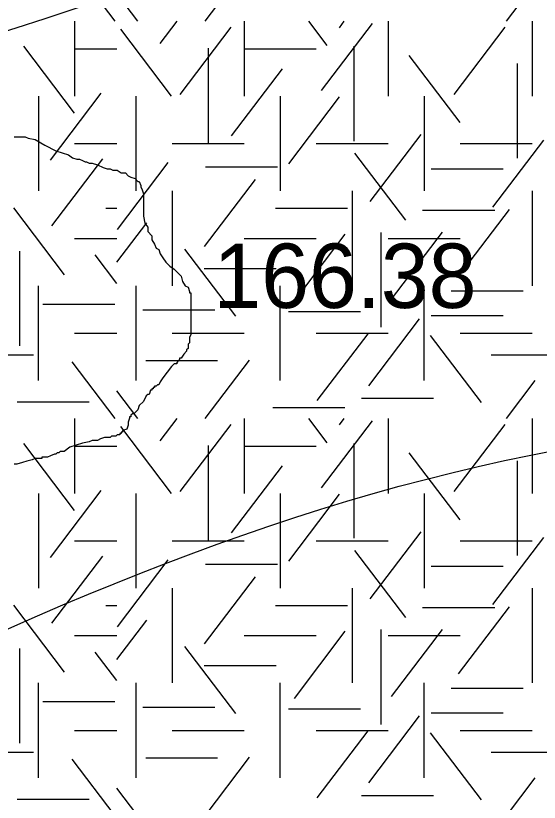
# Model space of a CAD drawing. Extents: x 419101 to 420177, y 4451541 to 4452254.
# Drawn here: x 419921.41 to 419931.17, y 4451588.77 to 4451603.44 of the extents above; entities that cross this region are included whole.
import ezdxf

# ---------------------------------------------------------------- set-up
doc = ezdxf.new("R2010")
doc.units = 0
for name, color, linetype in [('3_HALİHAZIR', 7, 'Continuous'), ('Level 3', 7, 'Continuous'), ('Level 41', 7, 'Continuous')]:
    doc.layers.add(name, color=color, linetype=linetype)

msp = doc.modelspace()

# ---------------------------------------------------------------- linework, layer by layer
at = {"layer": '3_HALİHAZIR'}
for points in [[(419839.353, 4451591.962), (419839.364, 4451591.971), (419844.374, 4451596.271), (419851.394, 4451601.551), (419855.474, 4451603.971), (419875.934, 4451611.761), (419891.494, 4451615.431), (419906.684, 4451617.851), (419924.462, 4451620.917), (419940.295, 4451639.301), (419940.435, 4451639.501), (419940.605, 4451639.681)], [(419830.585, 4451569.182), (419835.774, 4451573.831), (419840.974, 4451578.331), (419857.814, 4451590.841), (419892.084, 4451597.601), (419927.345, 4451605.321), (419938.763, 4451608.51), (419942.048, 4451608.213)], [(419823.158, 4451549.789), (419823.164, 4451549.79), (419829.854, 4451552.83), (419838.324, 4451557.73), (419864.054, 4451568.471), (419874.464, 4451571.841), (419888.954, 4451576.141), (419895.924, 4451578.691), (419906.074, 4451583.863), (419936.516, 4451595.874), (419942.649, 4451595.582)]]:
    msp.add_spline(points, degree=3, dxfattribs=at)
at = {"layer": 'Level 3'}
for points in [[(419921.378, 4451601.182), (419921.43, 4451601.182), (419921.508, 4451601.182), (419921.56, 4451601.182), (419921.586, 4451601.182), (419921.638, 4451601.156), (419921.768, 4451601.13), (419921.949, 4451601.026), (419922.157, 4451600.922), (419922.39, 4451600.844), (419922.468, 4451600.792), (419922.546, 4451600.766), (419922.598, 4451600.766), (419922.65, 4451600.74), (419922.701, 4451600.714), (419922.727, 4451600.714), (419922.779, 4451600.688), (419922.831, 4451600.688), (419922.935, 4451600.662), (419923.039, 4451600.61), (419923.116, 4451600.584), (419923.168, 4451600.584), (419923.22, 4451600.558), (419923.272, 4451600.558), (419923.298, 4451600.558), (419923.376, 4451600.507), (419923.454, 4451600.507), (419923.506, 4451600.455), (419923.557, 4451600.429), (419923.635, 4451600.403), (419923.687, 4451600.351), (419923.713, 4451600.351), (419923.739, 4451600.273), (419923.739, 4451600.247), (419923.765, 4451600.195), (419923.791, 4451600.117), (419923.791, 4451600.091), (419923.791, 4451600.013), (419923.791, 4451599.961), (419923.791, 4451599.883), (419923.791, 4451599.857), (419923.791, 4451599.779), (419923.791, 4451599.702), (419923.817, 4451599.572), (419923.869, 4451599.494), (419923.869, 4451599.416), (419923.947, 4451599.338), (419923.947, 4451599.26), (419923.998, 4451599.182), (419924.024, 4451599.104), (419924.076, 4451599.078), (419924.102, 4451599), (419924.154, 4451598.922), (419924.206, 4451598.845), (419924.284, 4451598.767), (419924.362, 4451598.715), (419924.413, 4451598.663), (419924.439, 4451598.637), (419924.491, 4451598.585), (419924.517, 4451598.481), (419924.569, 4451598.403), (419924.621, 4451598.377), (419924.647, 4451598.299), (419924.647, 4451598.273), (419924.673, 4451598.273), (419924.673, 4451598.247), (419924.673, 4451598.221), (419924.673, 4451598.169), (419924.673, 4451598.066), (419924.673, 4451598.014), (419924.673, 4451597.936), (419924.673, 4451597.858), (419924.673, 4451597.78), (419924.673, 4451597.702), (419924.673, 4451597.624), (419924.673, 4451597.572), (419924.673, 4451597.494), (419924.647, 4451597.442), (419924.647, 4451597.338), (419924.621, 4451597.312), (419924.621, 4451597.235), (419924.595, 4451597.209), (419924.595, 4451597.183), (419924.543, 4451597.131), (419924.491, 4451597.053), (419924.465, 4451597.053), (419924.465, 4451597.027), (419924.439, 4451597.001), (419924.413, 4451596.975), (419924.413, 4451596.949), (419924.388, 4451596.949), (419924.362, 4451596.949)], [(419924.362, 4451596.949), (419924.31, 4451596.897), (419924.154, 4451596.689), (419924.102, 4451596.611), (419924.076, 4451596.559), (419924.05, 4451596.559), (419924.024, 4451596.533), (419923.998, 4451596.533), (419923.998, 4451596.507), (419923.972, 4451596.507), (419923.972, 4451596.481), (419923.947, 4451596.481), (419923.947, 4451596.455), (419923.921, 4451596.455), (419923.895, 4451596.378), (419923.869, 4451596.378), (419923.843, 4451596.352), (419923.791, 4451596.248), (419923.713, 4451596.17), (419923.687, 4451596.092), (419923.609, 4451596.014), (419923.583, 4451596.014), (419923.557, 4451595.988), (419923.557, 4451595.962), (419923.531, 4451595.962), (419923.531, 4451595.936), (419923.506, 4451595.858), (419923.506, 4451595.806), (419923.48, 4451595.728), (419923.402, 4451595.702), (419923.402, 4451595.676), (419923.376, 4451595.676), (419923.376, 4451595.65), (419923.35, 4451595.65), (419923.35, 4451595.624), (419923.324, 4451595.624), (419923.298, 4451595.624), (419923.272, 4451595.599), (419923.246, 4451595.599), (419923.22, 4451595.599), (419923.194, 4451595.599), (419923.168, 4451595.573), (419923.142, 4451595.573), (419923.116, 4451595.573), (419923.09, 4451595.573), (419923.065, 4451595.573), (419922.987, 4451595.547), (419922.935, 4451595.521), (419922.857, 4451595.521), (419922.831, 4451595.521), (419922.779, 4451595.495), (419922.65, 4451595.469), (419922.416, 4451595.391), (419922.312, 4451595.313), (419922.234, 4451595.313), (419922.209, 4451595.287), (419922.183, 4451595.287), (419922.157, 4451595.261), (419922.131, 4451595.261), (419922.053, 4451595.235), (419922.001, 4451595.209), (419921.975, 4451595.209), (419921.949, 4451595.209), (419921.923, 4451595.209), (419921.897, 4451595.209), (419921.897, 4451595.183), (419921.871, 4451595.183), (419921.845, 4451595.183), (419921.768, 4451595.183), (419921.716, 4451595.157), (419921.612, 4451595.131), (419921.534, 4451595.105), (419921.43, 4451595.079), (419921.378, 4451595.079)]]:
    msp.add_lwpolyline(points, dxfattribs=at)
at = {"layer": 'Level 41'}
for p, q in [((419923.264, 4451603.337), (419922.462, 4451604.393)), ((419924.94, 4451603.337), (419925.769, 4451604.428)), ((419930.56, 4451603.337), (419931.097, 4451604.043)), ((419923.687, 4451603.337), (419923.293, 4451603.855)), ((419922.505, 4451603.337), (419922.505, 4451601.939)), ((419922.505, 4451603.337), (419922.505, 4451601.939)), ((419924.103, 4451602.92), (419924.42, 4451603.337)), ((419924.474, 4451601.974), (419925.423, 4451603.224)), ((419925.669, 4451603.337), (419925.669, 4451601.939)), ((419927.218, 4451602.885), (419926.874, 4451603.337)), ((419927.111, 4451602.043), (419928.061, 4451603.293)), ((419927.444, 4451603.217), (419927.535, 4451603.337)), ((419928.355, 4451603.337), (419928.355, 4451601.939)), ((419929.588, 4451601.974), (419930.537, 4451603.224)), ((419931.041, 4451603.337), (419931.041, 4451601.939)), ((419924.314, 4451601.939), (419923.365, 4451603.189)), ((419922.506, 4451601.623), (419921.557, 4451602.872)), ((419922.505, 4451602.823), (419923.293, 4451602.823)), ((419924.994, 4451602.835), (419924.994, 4451601.068)), ((419925.669, 4451602.823), (419927.012, 4451602.823)), ((419927.711, 4451602.87), (419927.711, 4451601.103)), ((419929.695, 4451601.448), (419928.746, 4451602.697)), ((419930.759, 4451602.549), (419930.759, 4451600.782)), ((419925.434, 4451601.202), (419926.383, 4451602.452)), ((419921.834, 4451601.939), (419921.834, 4451600.172)), ((419921.834, 4451601.939), (419921.834, 4451600.172)), ((419922.054, 4451600.746), (419923.003, 4451601.996)), ((419923.655, 4451600.172), (419923.655, 4451601.939)), ((419926.341, 4451601.939), (419926.341, 4451600.172)), ((419926.5, 4451600.677), (419927.449, 4451601.927)), ((419929.027, 4451601.939), (419929.027, 4451600.172)), ((419928.017, 4451599.976), (419928.968, 4451601.225)), ((419922.505, 4451601.055), (419923.293, 4451601.055)), ((419924.326, 4451601.055), (419925.669, 4451601.055)), ((419927.012, 4451601.055), (419928.355, 4451601.055)), ((419929.698, 4451601.055), (419931.041, 4451601.055)), ((419930.308, 4451599.871), (419931.257, 4451601.121)), ((419928.683, 4451599.626), (419927.733, 4451600.875)), ((419922.08, 4451599.52), (419923.03, 4451600.769)), ((419923.303, 4451599.451), (419924.252, 4451600.7)), ((419924.95, 4451600.621), (419926.293, 4451600.621)), ((419929.158, 4451600.585), (419930.501, 4451600.585)), ((419924.928, 4451599.134), (419925.877, 4451600.384)), ((419924.326, 4451600.172), (419924.326, 4451598.405)), ((419927.684, 4451600.172), (419927.684, 4451598.405)), ((419931.041, 4451600.172), (419931.041, 4451598.405)), ((419922.319, 4451598.608), (419921.37, 4451599.857)), ((419923.089, 4451599.848), (419923.293, 4451599.848)), ((419926.256, 4451599.848), (419927.599, 4451599.848)), ((419929.668, 4451598.574), (419930.618, 4451599.824)), ((419928.998, 4451599.815), (419930.341, 4451599.815)), ((419923.293, 4451598.842), (419923.852, 4451599.578)), ((419928.216, 4451599.4), (419928.216, 4451597.632)), ((419928.416, 4451598.154), (419929.365, 4451599.403)), ((419922.505, 4451599.288), (419923.293, 4451599.288)), ((419925.669, 4451599.288), (419927.012, 4451599.288)), ((419926.605, 4451598.118), (419927.555, 4451599.368)), ((419928.355, 4451599.288), (419929.698, 4451599.288)), ((419925.513, 4451597.837), (419924.564, 4451599.087)), ((419921.48, 4451599.05), (419921.48, 4451597.282)), ((419923.293, 4451598.448), (419922.887, 4451598.982)), ((419924.923, 4451598.728), (419926.266, 4451598.728)), ((419921.834, 4451596.637), (419921.834, 4451598.405)), ((419923.655, 4451596.637), (419923.655, 4451598.405)), ((419926.341, 4451596.637), (419926.341, 4451598.405)), ((419929.027, 4451596.637), (419929.027, 4451598.405)), ((419929.532, 4451598.307), (419930.875, 4451598.307)), ((419921.916, 4451598.062), (419923.259, 4451598.062)), ((419923.778, 4451597.956), (419925.121, 4451597.956)), ((419926.495, 4451597.922), (419927.838, 4451597.922)), ((419927.991, 4451596.54), (419928.94, 4451597.79)), ((419929.158, 4451597.851), (419930.501, 4451597.851)), ((419922.505, 4451597.521), (419923.293, 4451597.521)), ((419924.326, 4451597.521), (419925.669, 4451597.521)), ((419927.012, 4451597.521), (419928.355, 4451597.521)), ((419927.031, 4451596.261), (419927.98, 4451597.51)), ((419930.094, 4451596.226), (419929.144, 4451597.475)), ((419929.698, 4451597.521), (419931.041, 4451597.521)), ((419920.398, 4451597.114), (419921.741, 4451597.114)), ((419930.277, 4451597.114), (419931.62, 4451597.114)), ((419923.264, 4451595.928), (419922.462, 4451596.984)), ((419923.832, 4451597.01), (419925.174, 4451597.01)), ((419924.94, 4451595.928), (419925.769, 4451597.019)), ((419930.56, 4451595.928), (419931.097, 4451596.634)), ((419923.687, 4451595.928), (419923.293, 4451596.446)), ((419927.854, 4451596.309), (419929.197, 4451596.309)), ((419921.437, 4451596.24), (419922.78, 4451596.24)), ((419926.202, 4451596.134), (419927.545, 4451596.134)), ((419922.505, 4451595.928), (419922.505, 4451594.53)), ((419922.505, 4451595.928), (419922.505, 4451594.53)), ((419924.103, 4451595.511), (419924.42, 4451595.928)), ((419925.669, 4451595.928), (419925.669, 4451594.53)), ((419927.218, 4451595.476), (419926.874, 4451595.928)), ((419927.111, 4451594.634), (419928.061, 4451595.884)), ((419927.444, 4451595.808), (419927.535, 4451595.928)), ((419928.355, 4451595.928), (419928.355, 4451594.53)), ((419931.041, 4451595.928), (419931.041, 4451594.53)), ((419924.314, 4451594.53), (419923.365, 4451595.78)), ((419924.474, 4451594.565), (419925.423, 4451595.815)), ((419929.588, 4451594.565), (419930.537, 4451595.815)), ((419922.506, 4451594.214), (419921.557, 4451595.463)), ((419924.994, 4451595.426), (419924.994, 4451593.659)), ((419927.711, 4451595.461), (419927.711, 4451593.694)), ((419922.505, 4451595.414), (419923.293, 4451595.414)), ((419925.669, 4451595.414), (419927.012, 4451595.414)), ((419929.695, 4451594.039), (419928.746, 4451595.288)), ((419930.759, 4451595.14), (419930.759, 4451593.373)), ((419925.434, 4451593.793), (419926.383, 4451595.043)), ((419922.054, 4451593.337), (419923.003, 4451594.587)), ((419921.834, 4451594.53), (419921.834, 4451592.763)), ((419921.834, 4451594.53), (419921.834, 4451592.763)), ((419923.655, 4451592.763), (419923.655, 4451594.53)), ((419926.341, 4451594.53), (419926.341, 4451592.763)), ((419926.5, 4451593.268), (419927.449, 4451594.518)), ((419929.027, 4451594.53), (419929.027, 4451592.763)), ((419928.017, 4451592.567), (419928.968, 4451593.816)), ((419930.308, 4451592.462), (419931.257, 4451593.712)), ((419922.505, 4451593.646), (419923.293, 4451593.646)), ((419924.326, 4451593.646), (419925.669, 4451593.646)), ((419927.012, 4451593.646), (419928.355, 4451593.646)), ((419929.698, 4451593.646), (419931.041, 4451593.646)), ((419928.683, 4451592.217), (419927.733, 4451593.466)), ((419922.08, 4451592.111), (419923.03, 4451593.36)), ((419923.303, 4451592.042), (419924.252, 4451593.291)), ((419924.95, 4451593.212), (419926.293, 4451593.212)), ((419929.158, 4451593.176), (419930.501, 4451593.176)), ((419924.928, 4451591.725), (419925.877, 4451592.975)), ((419924.326, 4451592.763), (419924.326, 4451590.996)), ((419927.684, 4451592.763), (419927.684, 4451590.996)), ((419931.041, 4451592.763), (419931.041, 4451590.996)), ((419922.319, 4451591.199), (419921.37, 4451592.448)), ((419923.089, 4451592.439), (419923.293, 4451592.439)), ((419926.256, 4451592.439), (419927.599, 4451592.439)), ((419928.998, 4451592.406), (419930.341, 4451592.406)), ((419929.668, 4451591.165), (419930.618, 4451592.415)), ((419923.293, 4451591.433), (419923.852, 4451592.169)), ((419926.605, 4451590.709), (419927.555, 4451591.959)), ((419928.216, 4451591.991), (419928.216, 4451590.223)), ((419928.416, 4451590.745), (419929.365, 4451591.994)), ((419922.505, 4451591.879), (419923.293, 4451591.879)), ((419925.669, 4451591.879), (419927.012, 4451591.879)), ((419928.355, 4451591.879), (419929.698, 4451591.879)), ((419921.48, 4451591.641), (419921.48, 4451589.873)), ((419925.513, 4451590.428), (419924.564, 4451591.678)), ((419923.293, 4451591.039), (419922.887, 4451591.573)), ((419924.923, 4451591.319), (419926.266, 4451591.319)), ((419921.834, 4451589.228), (419921.834, 4451590.996)), ((419923.655, 4451589.228), (419923.655, 4451590.996)), ((419926.341, 4451589.228), (419926.341, 4451590.996)), ((419929.027, 4451589.228), (419929.027, 4451590.996)), ((419929.532, 4451590.898), (419930.875, 4451590.898)), ((419921.916, 4451590.653), (419923.259, 4451590.653)), ((419923.778, 4451590.547), (419925.121, 4451590.547)), ((419926.495, 4451590.513), (419927.838, 4451590.513)), ((419929.158, 4451590.442), (419930.501, 4451590.442)), ((419927.991, 4451589.131), (419928.94, 4451590.381)), ((419922.505, 4451590.112), (419923.293, 4451590.112)), ((419924.326, 4451590.112), (419925.669, 4451590.112)), ((419927.012, 4451590.112), (419928.355, 4451590.112)), ((419927.031, 4451588.852), (419927.98, 4451590.101)), ((419930.094, 4451588.817), (419929.144, 4451590.066)), ((419929.698, 4451590.112), (419931.041, 4451590.112)), ((419920.398, 4451589.705), (419921.741, 4451589.705)), ((419930.277, 4451589.705), (419931.62, 4451589.705)), ((419923.264, 4451588.519), (419922.462, 4451589.575)), ((419923.832, 4451589.601), (419925.174, 4451589.601)), ((419924.94, 4451588.519), (419925.769, 4451589.61)), ((419930.56, 4451588.519), (419931.097, 4451589.225)), ((419923.687, 4451588.519), (419923.293, 4451589.037)), ((419921.437, 4451588.831), (419922.78, 4451588.831)), ((419927.854, 4451588.9), (419929.197, 4451588.9))]:
    msp.add_line(p, q, dxfattribs=at)

# ---------------------------------------------------------------- texts
at = {"layer": '3_HALİHAZIR'}
msp.add_text('166.38 ', height=1.2, rotation=0.002, dxfattribs=at).set_placement((419925.094, 4451597.99))

doc.saveas('drawing.dxf')
